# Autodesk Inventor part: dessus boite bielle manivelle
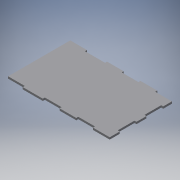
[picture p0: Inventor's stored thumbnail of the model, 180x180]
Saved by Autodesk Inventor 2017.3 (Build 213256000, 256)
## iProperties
Part Number: dessus boite bielle manivelle
Material: Générique
Document SubType Name: Modeling
Designer: ficho
Density: 1 g/cm^3
Appearance: Rouge
Author: ficho
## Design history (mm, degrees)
sketch "Esquisse1"
  geometry: L1 (130, -93)-(155, -93) reference; L2 (130, -93)-(130, -90); L3 (80, -93)-(105, -93); L4 (105, -93)-(105, -90); L5 (80, -93)-(80, -90); L6 (25, -93)-(55, -93); L7 (55, -93)-(55, -90); L8 (25, -93)-(25, -90); L9 (25, 0)-(25, 3); L10 (0, 3)-(25, 3); L11 (80, 0)-(80, 3); L12 (55, 3)-(80, 3); L13 (55, 0)-(55, 3); L14 (130, 0)-(130, 3); L15 (105, 3)-(130, 3); L16 (105, 0)-(105, 3); L17 (130, -90)-(105, -90); L18 (80, -90)-(55, -90); L19 (105, 0)-(80, 0); L20 (55, 0)-(25, 0); L21 (0, 3)-(0, -90); L22 (25, -90)-(0, -90); L23 (130, 0)-(155, 0) reference; L24 (155, -78)-(152, -78); L25 (152, -78)-(152, -53); L26 (152, -53)-(155, -53); L27 (155, -13)-(152, -13); L28 (152, -13)-(152, -38); L29 (152, -38)-(155, -38); L30 (155, -93)-(155, -78); L31 (155, -53)-(155, -38); L32 (155, -13)-(155, 0); L33 (137, -23.5)-(102, -23.5); L34 (137, -23.5)-(137, -20.5); L35 (102, -20.5)-(137, -20.5); L36 (102, -23.5)-(102, -20.5)
  constraints: 72 end point, 7 horizontal, 7 vertical, 3 perpendicular, 2 parallel, 1 collinear
  dimensions: "d2" = 3 distance of L25.end L26.end; "d3" = 25 distance of L24.end L25.end; "d4" = 3 distance of L29.end L28.end; "d5" = 25 distance of L28.end L27.end; "d6" = 15 distance between parallel lines of L1 L24; "d7" = 15 distance between parallel lines of L29 L26
extrude "Extrusion1" new body sketch "Esquisse1" distance "d0" = 3; taper "d1" = 0 deg
node "Solide1"
